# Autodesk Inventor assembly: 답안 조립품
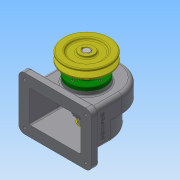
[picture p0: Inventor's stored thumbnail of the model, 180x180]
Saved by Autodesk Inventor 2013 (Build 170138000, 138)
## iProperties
Created: 2017-11
Part Number: 답안 조립품
Document SubType Name: Assembly
Designer: Administrator
Author: Administrator
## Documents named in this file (14)
- C:\Users\Administrator\Desktop\471108V1018\답안 조립품.iam
- C:\Users\Administrator\Desktop\471108V1018\본체.ipt
- C:\Users\Administrator\Desktop\471108V1018\V-벨트풀리.ipt
- C:\Users\Administrator\Desktop\471108V1018\뒤커버.ipt
- C:\Users\Administrator\Desktop\471108V1018\멈춤나사 - M4 x 10.ipt
- 멈춤나사 - M4 x 10.ipt
- C:\Users\Administrator\Desktop\471108V1018\베어링 6002.ipt
- C:\Users\Administrator\Desktop\471108V1018\볼트 M3 x 8.ipt
- C:\Users\Administrator\Desktop\471108V1018\스퍼기어.ipt
- C:\Users\Administrator\Desktop\471108V1018\앞커버.ipt
- C:\Users\Administrator\Desktop\471108V1018\오일 실 15 30 7.ipt
- C:\Users\Administrator\Desktop\471108V1018\축.ipt
- C:\Users\Administrator\Desktop\471108V1018\키 - 5 x 5 x 18.ipt
- C:\Users\Administrator\Desktop\471108V1018\키 - 6 x 6 x 22.ipt
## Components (1 placed, 1 different names)
1. V-벨트풀리:1
